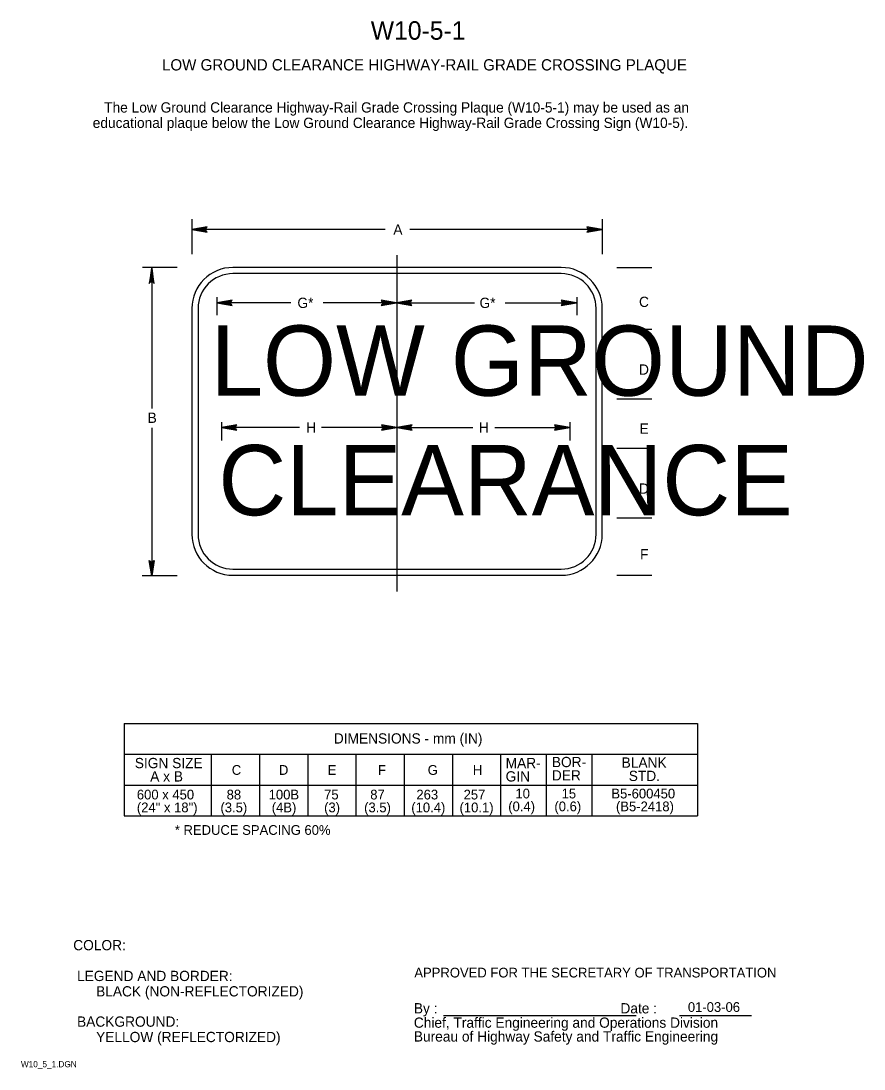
# Model space of a CAD drawing. Extents: x 0.013 to 0.218, y 0.004 to 0.259.
import ezdxf

# ---------------------------------------------------------------- set-up
doc = ezdxf.new("R2010")
doc.units = 0
for name, color, linetype in [('1', 7, 'Continuous'), ('2', 7, 'Continuous'), ('3', 7, 'Continuous'), ('4', 7, 'Continuous')]:
    doc.layers.add(name, color=color, linetype=linetype)

# ---------------------------------------------------------------- blocks, each defined once
blk = doc.blocks.new('RARROW')
at = {"layer": '3'}
for p, q in [((-2.156, 0.285), (-2.2665, 0.384625)), ((-2.2665, 0.384625), (0, 0)), ((0, 0), (-2.2665, -0.379125)), ((-2.156, 0.285), (-2.075625, 0.12075)), ((0, 0), (-2.156, 0.285)), ((-2.14975, -0.2705), (0, 0)), ((-2.075625, 0.12075), (0, 0)), ((0, 0), (-2.074, -0.108)), ((-2.2665, -0.379125), (-2.14975, -0.2705)), ((-2.074, -0.108), (-2.14975, -0.2705))]:
    blk.add_line(p, q, dxfattribs=at)

msp = doc.modelspace()

# ---------------------------------------------------------------- linework, layer by layer
at = {"layer": '1'}
for p, q in [((0.1041, 0.20228), (0.1041, 0.12033)), ((0.06026, 0.19202), (0.06026, 0.18762)), ((0.14796, 0.19202), (0.14796, 0.18762)), ((0.06138, 0.16152), (0.06138, 0.15707)), ((0.14629, 0.16152), (0.14629, 0.15707)), ((0.11544, 0.01695), (0.16242, 0.01695)), ((0.17295, 0.01695), (0.19056, 0.01695))]:
    msp.add_line(p, q, dxfattribs=at)
at = {"layer": '3'}
for p, q in [((0.05416, 0.211), (0.05416, 0.2025)), ((0.15416, 0.211), (0.15416, 0.2025)), ((0.10128, 0.2085), (0.05412, 0.2085)), ((0.15416, 0.2085), (0.10731, 0.2085)), ((0.05059, 0.19925), (0.0421, 0.19925)), ((0.04437, 0.19925), (0.04437, 0.16487)), ((0.14416, 0.19925), (0.06416, 0.19925)), ((0.15772, 0.19925), (0.16622, 0.19925)), ((0.14416, 0.19775), (0.06416, 0.19775)), ((0.05416, 0.18925), (0.05416, 0.13425)), ((0.05566, 0.18925), (0.05566, 0.13425)), ((0.07825, 0.19063), (0.06036, 0.19063)), ((0.104, 0.19063), (0.08613, 0.19063)), ((0.10411, 0.19063), (0.123, 0.19063)), ((0.1305, 0.19063), (0.14796, 0.19063)), ((0.15266, 0.13425), (0.15266, 0.18925)), ((0.15416, 0.13425), (0.15416, 0.18925)), ((0.15772, 0.18425), (0.16622, 0.18425)), ((0.15772, 0.16725), (0.16622, 0.16725)), ((0.04437, 0.16018), (0.04437, 0.12412)), ((0.08041, 0.16025), (0.06137, 0.16025)), ((0.10412, 0.16025), (0.08576, 0.16025)), ((0.10412, 0.16025), (0.12265, 0.16025)), ((0.128, 0.16025), (0.14625, 0.16025)), ((0.15772, 0.15525), (0.16622, 0.15525)), ((0.15772, 0.13825), (0.16622, 0.13825)), ((0.06416, 0.12575), (0.14416, 0.12575)), ((0.05056, 0.12414), (0.04206, 0.12414)), ((0.06416, 0.12425), (0.14416, 0.12425)), ((0.15772, 0.12425), (0.16622, 0.12425)), ((0.03762, 0.08812), (0.03762, 0.06563)), ((0.03762, 0.08812), (0.17738, 0.08812)), ((0.17738, 0.08812), (0.17738, 0.06563)), ((0.03762, 0.08063), (0.17738, 0.08063)), ((0.05888, 0.08063), (0.05888, 0.06563)), ((0.07063, 0.08063), (0.07063, 0.06563)), ((0.08238, 0.08063), (0.08238, 0.06563)), ((0.09413, 0.08063), (0.09413, 0.06563)), ((0.10587, 0.08063), (0.10587, 0.06563)), ((0.11763, 0.08063), (0.11763, 0.06563)), ((0.12937, 0.08063), (0.12937, 0.06563)), ((0.1405, 0.08063), (0.1405, 0.06563)), ((0.15163, 0.08063), (0.15163, 0.06563)), ((0.03762, 0.07312), (0.17738, 0.07312)), ((0.03762, 0.06563), (0.17738, 0.06563))]:
    msp.add_line(p, q, dxfattribs=at)
for centre, radius, start, end in [((0.06416, 0.18925), 0.01, 90, 180), ((0.14416, 0.18925), 0.01, 0, 90), ((0.06416, 0.18925), 0.0085, 90, 180), ((0.14416, 0.18925), 0.0085, 0, 90), ((0.06416, 0.13425), 0.01, 180, 270), ((0.06416, 0.13425), 0.0085, 180, 270), ((0.14416, 0.13425), 0.01, 270, 0), ((0.14416, 0.13425), 0.0085, 270, 0)]:
    msp.add_arc(centre, radius, start, end, dxfattribs=at)

# ---------------------------------------------------------------- block references
at = {"layer": '3', "xscale": 0.0016545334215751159}
for p, yscale, rotation in [((0.05412, 0.2085), -0.0016366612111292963, -180), ((0.04437, 0.19912), -0.0016366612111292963, 90.00000000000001), ((0.06025, 0.19063), -0.0016366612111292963, -180), ((0.104, 0.19063), -0.0016366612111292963, -180), ((0.06137, 0.16025), -0.0016366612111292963, -180), ((0.10412, 0.16025), -0.0016366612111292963, -180), ((0.04437, 0.12412), 0.0016366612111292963, -90.00000000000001)]:
    msp.add_blockref('RARROW', p, dxfattribs=dict(at, yscale=yscale, rotation=rotation))
at = {"layer": '3', "xscale": 0.0016545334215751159, "yscale": -0.0016366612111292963}
for p in [(0.15413, 0.2085), (0.104, 0.19063), (0.14788, 0.19063), (0.10412, 0.16025), (0.14625, 0.16025)]:
    msp.add_blockref('RARROW', p, dxfattribs=at)

# ---------------------------------------------------------------- texts
at = {"layer": '1'}
for s, height, p in [('W10-5-1', 0.0045, (0.09775, 0.25475)), ('LOW GROUND CLEARANCE HIGHWAY-RAIL GRADE CROSSING PLAQUE', 0.0027503, (0.04688, 0.24725)), ('LOW GROUND', 0.017125, (0.05875, 0.168)), ('CLEARANCE', 0.017125, (0.06062, 0.13887)), ('* REDUCE SPACING 60%', 0.0023752, (0.05, 0.061)), ('COLOR:', 0.0025, (0.02525, 0.03288)), ('APPROVED FOR THE SECRETARY OF TRANSPORTATION', 0.0023752, (0.10837, 0.02625)), (' LEGEND AND BORDER:', 0.0024998, (0.02525, 0.02538)), ('      BLACK (NON-REFLECTORIZED)', 0.0024998, (0.02525, 0.02163)), ('By :                                                Date :', 0.0024998, (0.10825, 0.0175)), (' BACKGROUND:', 0.0024998, (0.02525, 0.01425)), ('Chief, Traffic Engineering and Operations Division', 0.0024998, (0.10825, 0.014)), ('      YELLOW (REFLECTORIZED)', 0.0024998, (0.02525, 0.0105)), ('Bureau of Highway Safety and Traffic Engineering', 0.0024998, (0.10825, 0.01063)), ('W10_5_1.DGN', 0.0015, (0.0125, 0.00438))]:
    msp.add_text(s, height=height, dxfattribs=at).set_placement(p)
at = {"layer": '2'}
for s, p in [('   The Low Ground Clearance Highway-Rail Grade Crossing Plaque (W10-5-1) may be used as an', (0.03, 0.237)), ('educational plaque below the Low Ground Clearance Highway-Rail Grade Crossing Sign (W10-5).', (0.03, 0.23325))]:
    msp.add_text(s, height=0.0024998, dxfattribs=at).set_placement(p)
at = {"layer": '3'}
for s, height, p in [('A', 0.0025, (0.10325, 0.20725)), ('G*', 0.0025, (0.07988, 0.18938)), ('G*', 0.0025, (0.12425, 0.18938)), ('C', 0.0025, (0.16312, 0.18963)), ('D', 0.0025, (0.16312, 0.17313)), ('B', 0.0025, (0.04338, 0.16137)), ('H', 0.0025, (0.082, 0.159)), ('H', 0.0025, (0.12412, 0.159)), ('E', 0.0025, (0.16325, 0.15875)), ('D', 0.0025, (0.16312, 0.14413)), ('F', 0.0025, (0.16337, 0.12812)), ('DIMENSIONS - mm (IN)', 0.0024998, (0.08875, 0.08325)), ('SIGN SIZE', 0.0025, (0.04025, 0.07725)), ('MAR-', 0.0025, (0.13062, 0.07725)), ('BOR-', 0.0025, (0.14188, 0.0775)), ('BLANK', 0.0025, (0.15888, 0.07737)), ('C', 0.00238, (0.06388, 0.07562)), ('D', 0.00238, (0.07537, 0.07562)), ('E', 0.00238, (0.08725, 0.07562)), ('F', 0.00238, (0.0995, 0.07562)), ('G', 0.00238, (0.11163, 0.07562)), ('H', 0.00238, (0.12262, 0.07562)), ('DER', 0.0025, (0.14188, 0.07425)), ('STD.', 0.0025, (0.16062, 0.07412)), ('A x B', 0.0025, (0.044, 0.074)), ('GIN', 0.0025, (0.13062, 0.074)), ('600 x 450', 0.002375, (0.04075, 0.06963)), ('88', 0.002375, (0.06263, 0.06963)), ('100B', 0.002375, (0.07287, 0.06963)), ('75', 0.002375, (0.08638, 0.06963)), ('87', 0.002375, (0.09763, 0.06963)), ('263', 0.002375, (0.10887, 0.06963)), ('257', 0.002375, (0.12037, 0.06963)), ('10', 0.002375, (0.133, 0.06988)), ('15', 0.002375, (0.14425, 0.06988)), ('B5-600450', 0.002375, (0.15638, 0.06988)), ('(24" x 18")', 0.0023752, (0.04075, 0.0665)), ('(3.5)', 0.002375, (0.06112, 0.0665)), ('(4B)', 0.002375, (0.07362, 0.0665)), ('(3)', 0.002375, (0.08638, 0.0665)), ('(3.5)', 0.002375, (0.09613, 0.0665)), ('(10.4)', 0.002375, (0.10762, 0.0665)), ('(10.1)', 0.002375, (0.11938, 0.0665)), ('(0.4)', 0.002375, (0.13125, 0.06675)), ('(0.6)', 0.002375, (0.1425, 0.06675)), ('(B5-2418)', 0.002375, (0.1575, 0.06675))]:
    msp.add_text(s, height=height, dxfattribs=at).set_placement(p)
at = {"layer": '4'}
msp.add_text('01-03-06', height=0.002375, dxfattribs=at).set_placement((0.17502, 0.01786))

doc.saveas('drawing.dxf')
